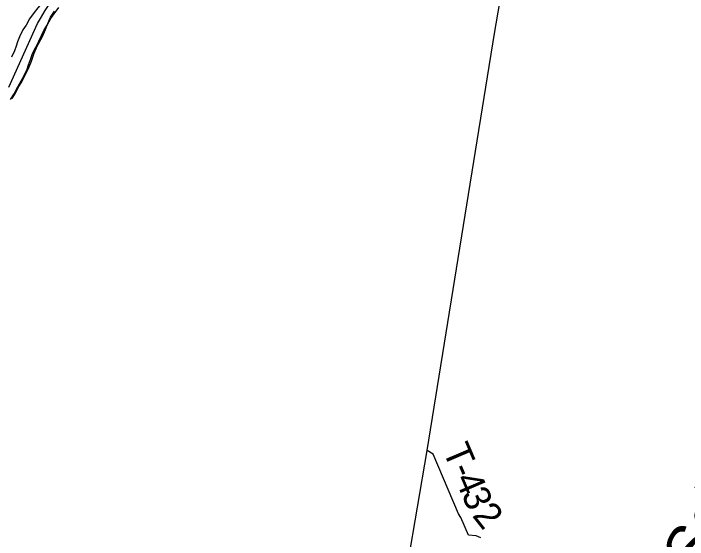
# Model space of a CAD drawing. Extents: x 1578669 to 1989827, y 208020 to 553079.
# Drawn here: x 1821165 to 1828673, y 394363 to 400223 of the extents above; entities that cross this region are included whole.
import ezdxf

# ---------------------------------------------------------------- set-up
doc = ezdxf.new("R2010")
doc.units = 0
for name, color, linetype in [('GM_X_Major_River_Text', 7, 'Continuous'), ('GM_X_Minor_River', 7, 'Continuous'), ('GM_X_State_Route', 7, 'Continuous'), ('GM_X_Township_Road', 7, 'Continuous'), ('GM_X_Township_Road_Text', 7, 'Continuous'), ('GM_X_US_Route', 7, 'Continuous')]:
    doc.layers.add(name, color=color, linetype=linetype)

msp = doc.modelspace()

# ---------------------------------------------------------------- linework, layer by layer
at = {"layer": 'GM_X_Minor_River'}
for points in [[(1821494.2, 400487.9), (1821481.9, 400338.6), (1821436.1, 400284.2), (1821394.3, 400233.9), (1821342.5, 400161.5), (1821306.8, 400091.1), (1821269, 400040.8), (1821233.3, 399964.5), (1821211.5, 399908.2), (1821195.7, 399858.1), (1821175.9, 399807.8), (1821144.2, 399737.5)], [(1821132.3, 399264.4), (1821174.1, 399328.8), (1821213.8, 399405.2), (1821249.5, 399471.5), (1821283.3, 399531.8), (1821317, 399602.1), (1821332.8, 399652.3), (1821354.6, 399710.5), (1821378.3, 399776.8), (1821416, 399849.2), (1821445.8, 399915.5), (1821475.5, 399977.8), (1821507.3, 400040.1), (1821539.1, 400094.3), (1821580.8, 400166.7), (1821618.6, 400219), (1821670.4, 400289.5)], [(1821150.3, 399276.5), (1821186, 399336.9), (1821225.8, 399409.2), (1821257.6, 399461.5), (1821287.3, 399521.8), (1821313.1, 399572), (1821338.9, 399628.3), (1821366.7, 399692.6), (1821396.3, 399780.9), (1821422.1, 399839.2), (1821447.9, 399891.4), (1821487.6, 399967.8), (1821521.3, 400044.1), (1821547, 400110.4), (1821578.8, 400180.8), (1821620.5, 400249.1)]]:
    msp.add_lwpolyline(points, dxfattribs=at)
at = {"layer": 'GM_X_State_Route'}
msp.add_lwpolyline([(1821112, 399400.3), (1821433.3, 400111.2), (1821464.3, 400168.7), (1821516.7, 400257.5), (1821596.6, 400376.8), (1821660.5, 400451.6)], dxfattribs=at)
at = {"layer": 'GM_X_Township_Road'}
msp.add_lwpolyline([(1826370.4, 394382.2), (1826318.4, 394403), (1826232.4, 394410.8), (1826149.1, 394608.7), (1826123.1, 394647.8), (1825839.4, 395314.4), (1825771.7, 395356.1)], dxfattribs=at)
at = {"layer": 'GM_X_US_Route'}
msp.add_lwpolyline([(1825021.3, 391110.7), (1825112.3, 391603.9), (1825343.2, 392830.7), (1825771.7, 395356.1), (1826523.4, 400000.8), (1827176.2, 403802.3)], dxfattribs=at)

# ---------------------------------------------------------------- texts
at = {"layer": 'GM_X_Major_River_Text'}
msp.add_text('Scioto', height=500.01, rotation=61.09416, dxfattribs=at).set_placement((1828809.6, 393963.8))
at = {"layer": 'GM_X_Township_Road_Text'}
for s, rotation, p in [('T', 293.05755, (1825942.2, 395358.2)), ('-', 293.05778, (1826029.9, 395152.1)), ('4', 293.07009, (1826077.8, 395039.7)), ('3', 293.37396, (1826150.3, 394869.4)), ('2', 308.41561, (1826267, 394627.7))]:
    msp.add_text(s, height=300, rotation=rotation, dxfattribs=at).set_placement(p)

doc.saveas('drawing.dxf')
